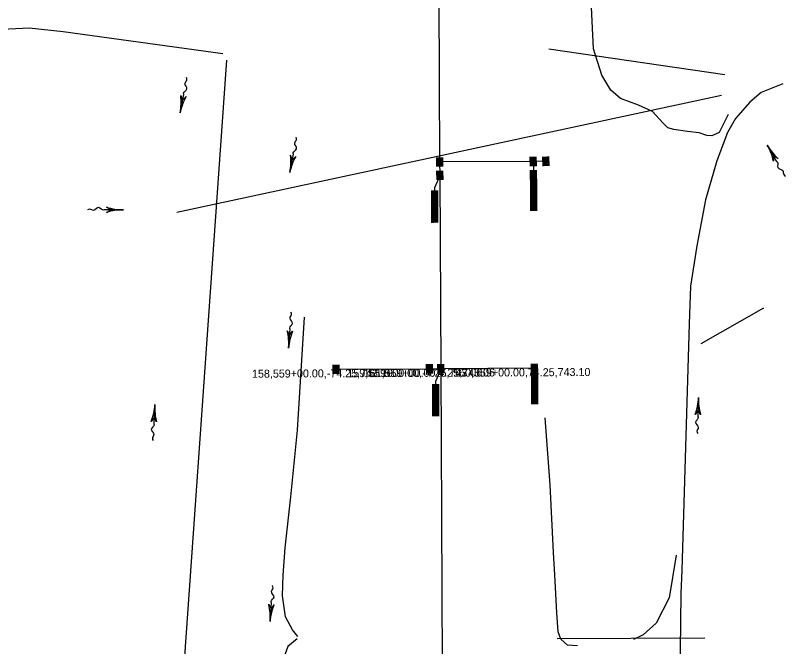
# Model space of a CAD drawing. Extents: x 593481 to 595602, y 151646 to 157396.
# Drawn here: x 594038 to 594615, y 154967 to 155440 of the extents above; entities that cross this region are included whole.
import ezdxf

# ---------------------------------------------------------------- set-up
doc = ezdxf.new("R2010")
doc.units = 0
for name, color, linetype in [('P_ALI_50_Equation', 7, 'Continuous'), ('P_DRN_Flow', 7, 'Continuous'), ('P_DRN_Inlet', 7, 'Continuous'), ('P_DRN_Pipes', 7, 'Continuous'), ('P_DRN_SS_UG', 7, 'Continuous')]:
    doc.layers.add(name, color=color, linetype=linetype)

msp = doc.modelspace()

# ---------------------------------------------------------------- linework, layer by layer
at = {"layer": 'P_DRN_Flow'}
for p, q in [((594161.19, 155367.03), (594163.89, 155380.89)), ((594601.12, 155342.88), (594608.19, 155330.65)), ((594243.38, 155322.25), (594246.08, 155336.12)), ((594118.75, 155294.28), (594104.62, 155294.42)), ((594242.48, 155190.75), (594243.54, 155204.84)), ((594142.3, 155148.35), (594141.41, 155134.25)), ((594549.65, 155153.69), (594549.17, 155139.57)), ((594228.61, 154985.82), (594229.67, 154999.91))]:
    msp.add_line(p, q, dxfattribs=at)
for points in [[(594161.67, 155379.97), (594163.02, 155376.45), (594165.59, 155379.21)], [(594243.86, 155335.19), (594245.21, 155331.67), (594247.79, 155334.43)], [(594609.26, 155332.81), (594605.93, 155334.58), (594605.8, 155330.8)], [(594105.94, 155292.41), (594109.16, 155294.38), (594105.97, 155296.41)], [(594241.45, 155203.66), (594243.2, 155200.32), (594245.44, 155203.37)], [(594551.21, 155140.83), (594549.32, 155144.1), (594547.22, 155140.96)], [(594143.49, 155135.45), (594141.7, 155138.77), (594139.5, 155135.7)], [(594227.57, 154998.73), (594229.32, 154995.39), (594231.56, 154998.44)]]:
    msp.add_lwpolyline(points, dxfattribs=at)
for centre, start, end in [((594120, 155375.03), 349.00666, 6.76898), ((594202.38, 155359.02), 151.24434, 169.00666), ((594637.44, 155363.89), 210.05001, 227.81233), ((594564.8, 155321.87), 12.2877, 30.05001), ((594202.2, 155330.25), 349.00666, 6.76898), ((594284.57, 155314.25), 151.24434, 169.00666), ((594118.34, 155252.33), 89.4352, 107.19752), ((594119.17, 155336.24), 251.67288, 269.4352), ((594200.65, 155193.9), 355.6942, 13.45652), ((594284.32, 155187.6), 157.93188, 175.6942), ((594100.43, 155151), 338.61546, 356.37778), ((594184.17, 155145.7), 176.37778, 194.1401), ((594507.72, 155155.12), 340.28381, 358.04613), ((594591.58, 155152.26), 178.04613, 195.80845), ((594186.77, 154988.97), 355.6942, 13.45652), ((594270.44, 154982.67), 157.93188, 175.6942)]:
    msp.add_arc(centre, 41.96, start, end, dxfattribs=at)
for points in [[(594163.89, 155380.9), (594163.73, 155381.73), (594166.26, 155384.91), (594164.86, 155389.18), (594166.32, 155391.78), (594166.03, 155393.59)], [(594246.08, 155336.12), (594245.92, 155336.95), (594248.46, 155340.13), (594247.05, 155344.4), (594248.51, 155347), (594248.22, 155348.81)], [(594608.19, 155330.65), (594608.86, 155330.13), (594609.04, 155326.06), (594612.9, 155323.76), (594613.5, 155320.85), (594614.91, 155319.67)], [(594104.62, 155294.42), (594103.84, 155294.12), (594100.24, 155296.03), (594096.3, 155293.88), (594093.48, 155294.85), (594091.75, 155294.24)], [(594243.54, 155204.84), (594243.29, 155205.65), (594245.44, 155209.11), (594243.54, 155213.19), (594244.69, 155215.93), (594244.2, 155217.7)], [(594549.17, 155139.57), (594549.45, 155138.77), (594547.45, 155135.23), (594549.51, 155131.23), (594548.47, 155128.44), (594549.04, 155126.69)], [(594141.41, 155134.25), (594141.67, 155133.44), (594139.56, 155129.96), (594141.51, 155125.9), (594140.39, 155123.14), (594140.91, 155121.38)], [(594229.67, 154999.91), (594229.41, 155000.72), (594231.56, 155004.18), (594229.67, 155008.26), (594230.82, 155011), (594230.32, 155012.77)]]:
    msp.add_spline(points, degree=3, dxfattribs=at)
at = {"layer": 'P_DRN_Inlet'}
for p, q in [((594353.65, 155326.8), (594353.62, 155333.67)), ((594354.55, 155326.8), (594354.52, 155333.67)), ((594355.45, 155326.8), (594355.42, 155333.68)), ((594356.35, 155326.81), (594356.32, 155333.68)), ((594357.25, 155326.81), (594357.22, 155333.69)), ((594358.15, 155326.82), (594358.12, 155333.69)), ((594423.65, 155327.15), (594423.62, 155334.03)), ((594424.55, 155327.16), (594424.52, 155334.03)), ((594425.45, 155327.16), (594425.42, 155334.04)), ((594426.35, 155327.17), (594426.32, 155334.04)), ((594427.25, 155327.17), (594427.22, 155334.05)), ((594428.15, 155327.18), (594428.12, 155334.05)), ((594433.28, 155327.15), (594432.9, 155334.01)), ((594434.18, 155327.2), (594433.8, 155334.06)), ((594435.08, 155327.24), (594434.7, 155334.11)), ((594435.98, 155327.29), (594435.6, 155334.16)), ((594436.88, 155327.34), (594436.5, 155334.21)), ((594437.78, 155327.39), (594437.4, 155334.26)), ((594353.7, 155316.81), (594353.67, 155323.68)), ((594354.6, 155316.81), (594354.57, 155323.68)), ((594355.5, 155316.81), (594355.47, 155323.69)), ((594356.4, 155316.82), (594356.37, 155323.69)), ((594357.3, 155316.82), (594357.27, 155323.7)), ((594358.2, 155316.83), (594358.17, 155323.7)), ((594423.72, 155317.19), (594423.69, 155324.07)), ((594424.62, 155317.2), (594424.59, 155324.07)), ((594425.52, 155317.2), (594425.49, 155324.08)), ((594426.42, 155317.21), (594426.39, 155324.08)), ((594427.32, 155317.21), (594427.29, 155324.09)), ((594428.22, 155317.22), (594428.19, 155324.09)), ((594423.72, 155317.63), (594423.84, 155293.63)), ((594424.62, 155317.64), (594424.74, 155293.64)), ((594425.52, 155317.64), (594425.64, 155293.64)), ((594426.42, 155317.64), (594426.54, 155293.65)), ((594427.32, 155317.65), (594427.44, 155293.65)), ((594428.22, 155317.65), (594428.34, 155293.65)), ((594349.49, 155308.73), (594349.61, 155284.73)), ((594350.39, 155308.73), (594350.51, 155284.73)), ((594351.29, 155308.73), (594351.41, 155284.74)), ((594352.19, 155308.74), (594352.31, 155284.74)), ((594353.09, 155308.74), (594353.21, 155284.74)), ((594353.99, 155308.75), (594354.11, 155284.75)), ((594275.95, 155171.39), (594275.91, 155178.27)), ((594276.85, 155171.4), (594276.81, 155178.27)), ((594277.75, 155171.4), (594277.71, 155178.28)), ((594278.65, 155171.41), (594278.61, 155178.28)), ((594279.55, 155171.41), (594279.51, 155178.29)), ((594280.45, 155171.42), (594280.41, 155178.29)), ((594345.95, 155171.75), (594345.91, 155178.63)), ((594346.85, 155171.76), (594346.81, 155178.63)), ((594347.75, 155171.76), (594347.71, 155178.64)), ((594348.65, 155171.77), (594348.61, 155178.64)), ((594349.55, 155171.77), (594349.51, 155178.65)), ((594350.45, 155171.78), (594350.41, 155178.65)), ((594354.45, 155171.8), (594354.41, 155178.67)), ((594355.35, 155171.8), (594355.31, 155178.68)), ((594356.25, 155171.81), (594356.21, 155178.68)), ((594357.15, 155171.81), (594357.11, 155178.69)), ((594358.05, 155171.82), (594358.01, 155178.69)), ((594358.95, 155171.82), (594358.91, 155178.69)), ((594424.45, 155172.16), (594424.41, 155179.03)), ((594425.35, 155172.16), (594425.31, 155179.04)), ((594426.25, 155172.17), (594426.21, 155179.04)), ((594427.15, 155172.17), (594427.11, 155179.05)), ((594428.05, 155172.17), (594428.01, 155179.05)), ((594428.95, 155172.18), (594428.91, 155179.05)), ((594424.44, 155172.59), (594424.56, 155148.6)), ((594425.34, 155172.6), (594425.46, 155148.6)), ((594426.24, 155172.6), (594426.36, 155148.6)), ((594427.14, 155172.61), (594427.26, 155148.61)), ((594428.04, 155172.61), (594428.16, 155148.61)), ((594428.94, 155172.62), (594429.06, 155148.62)), ((594350.22, 155163.67), (594350.34, 155139.67)), ((594351.12, 155163.68), (594351.24, 155139.68)), ((594352.02, 155163.68), (594352.14, 155139.68)), ((594352.92, 155163.69), (594353.04, 155139.69)), ((594353.82, 155163.69), (594353.94, 155139.69)), ((594354.72, 155163.7), (594354.84, 155139.7))]:
    msp.add_line(p, q, dxfattribs=at)
for points in [[(594356.89, 155329.25), (594356.88, 155331.25), (594354.88, 155331.24), (594354.89, 155329.24)], [(594426.89, 155329.61), (594426.88, 155331.61), (594424.88, 155331.6), (594424.89, 155329.6)], [(594436.39, 155329.76), (594436.28, 155331.75), (594434.29, 155331.65), (594434.4, 155329.65)], [(594356.94, 155319.26), (594356.93, 155321.26), (594354.93, 155321.25), (594354.94, 155319.25)], [(594426.96, 155319.65), (594426.95, 155321.65), (594424.95, 155321.64), (594424.96, 155319.64)], [(594425, 155312.91), (594425.07, 155298.37), (594427.07, 155298.38), (594427, 155312.92)], [(594350.76, 155304.01), (594350.84, 155289.46), (594352.84, 155289.47), (594352.76, 155304.02)], [(594279.19, 155173.85), (594279.18, 155175.85), (594277.18, 155175.84), (594277.19, 155173.84)], [(594349.19, 155174.21), (594349.18, 155176.21), (594347.18, 155176.2), (594347.19, 155174.2)], [(594357.69, 155174.25), (594357.68, 155176.25), (594355.68, 155176.24), (594355.69, 155174.24)], [(594427.69, 155174.61), (594427.68, 155176.61), (594425.68, 155176.6), (594425.69, 155174.6)], [(594425.71, 155167.87), (594425.79, 155153.33), (594427.79, 155153.34), (594427.71, 155167.88)], [(594351.49, 155158.95), (594351.57, 155144.41), (594353.57, 155144.42), (594353.49, 155158.96)]]:
    msp.add_lwpolyline(points, close=True, dxfattribs=at)
at = {"layer": 'P_DRN_Pipes'}
for p, q in [((594437.6, 155415.01), (594569.29, 155395.66)), ((594158.67, 155292.68), (594566.79, 155380.23)), ((594551.54, 155194.26), (594598.53, 155220.88)), ((594443.69, 154973.11), (594554.46, 154973.67))]:
    msp.add_line(p, q, dxfattribs=at)
at = {"layer": 'P_DRN_SS_UG'}
for p, q in [((594355.89, 155330.24), (594355.09, 155485.25)), ((594425.88, 155330.6), (594355.89, 155330.24)), ((594355.94, 155320.25), (594355.89, 155330.24)), ((594435.34, 155330.7), (594425.88, 155330.6)), ((594425.88, 155330.6), (594425.94, 155320.6)), ((594356.68, 155175.25), (594355.94, 155320.25)), ((594425.96, 155319.64), (594425.97, 155317.64)), ((594278.18, 155174.84), (594348.18, 155175.2)), ((594348.18, 155175.2), (594356.68, 155175.25)), ((594426.68, 155175.61), (594356.68, 155175.25)), ((594358.22, 154875.25), (594356.68, 155175.25)), ((594426.68, 155175.61), (594426.7, 155172.61))]:
    msp.add_line(p, q, dxfattribs=at)
for points in [[(594571.92, 155365.74), (594565.14, 155352.43), (594559.64, 155349.73), (594555.87, 155350.12), (594550.25, 155352.04), (594541.37, 155353.15), (594531.15, 155354.6), (594526.59, 155355.9), (594522.9, 155359.56), (594515.29, 155368.06), (594504.61, 155372.79), (594491.24, 155377.87), (594483.84, 155384), (594477.1, 155395.15), (594470.86, 155414.95), (594468.94, 155456.73), (594466.21, 155498.03)], [(594193.09, 155411.34), (594073.54, 155427.86), (594048.1, 155430.58), (594022.56, 155429.15), (594004.52, 155425.45), (593990.2, 155419.58), (593976.72, 155409.53), (593963.18, 155397.41), (593953.35, 155382.07), (593943.75, 155338.68), (593941.24, 155313.82), (593931.56, 155304.71), (593921.12, 155302.9), (593896.63, 155305.59), (593891.96, 155307.79), (593879.74, 155310.17), (593860.02, 155314.83), (593844.02, 155317.31), (593827.14, 155321.89), (593814.99, 155327.39)], [(594195.87, 155406.63), (594155.86, 154839.17), (594136.12, 154647.32), (594125.75, 154586.3), (594119.28, 154562.31), (594104.8, 154521.76), (594093.35, 154507.25), (594075.71, 154498.55), (594048.65, 154492.71), (593981.57, 154485.26), (593546.85, 154493.19), (593538.17, 154494.28), (593526.38, 154497.62), (593514.24, 154502.72), (593501.23, 154504.79), (593491.32, 154504.17), (593484.5, 154500.86), (593481.17, 154494.41)], [(594612.95, 155388.89), (594596.71, 155382.2), (594588.1, 155375.16), (594577.39, 155362.81), (594571.35, 155352.38), (594563.26, 155330.97), (594554.94, 155301.9), (594548.34, 155267.44), (594543.77, 155237.13), (594542.73, 155208.88), (594537.26, 155024.38), (594536.51, 155006.73), (594535.72, 154943.23), (594533.09, 154881.6), (594531.45, 154816.64), (594529.67, 154746.17)], [(594355.94, 155320.25), (594351.74, 155310.74), (594351.75, 155308.74)], [(594249.5, 154974.47), (594245.36, 154979.68), (594240.25, 154989.23), (594237.97, 155005.19), (594238.36, 155020.5), (594239.95, 155041.07), (594244.13, 155079.25), (594249.14, 155129.18), (594254.49, 155213.86)], [(594356.68, 155175.25), (594352.48, 155165.69), (594352.49, 155163.69)], [(594459.03, 154967.51), (594451.56, 154968.01), (594446.5, 154972.57), (594444.41, 154978.14), (594443.43, 154992.33), (594442.07, 155020.78), (594440.92, 155037.43), (594438.56, 155088.15), (594434.63, 155138.37)], [(594532.95, 155035.61), (594527.56, 155003.52), (594517.93, 154984.63), (594508.17, 154975.76), (594500.89, 154972.46)], [(594248.94, 154972.9), (594241.91, 154967.19), (594238.79, 154958.94), (594235.75, 154930.84), (594230.88, 154901.44), (594227.52, 154859.43), (594221.1, 154817.5), (594214.83, 154781.45), (594209.84, 154735.27), (594200.1, 154653.01), (594191.65, 154590.92), (594189.63, 154541.3), (594190.82, 154497.49), (594193.99, 154473.57)]]:
    msp.add_lwpolyline(points, dxfattribs=at)

# ---------------------------------------------------------------- texts
at = {"layer": 'P_ALI_50_Equation'}
for s, p in [('158,559+00.00,-74.25,743.10', (594215.08, 155168.52)), ('159,559+00.00,-4.25,743.06', (594286.52, 155168.89)), ('161,559+00.00,4.25,743.06', (594298.75, 155168.95)), ('160,559+00.00,74.25,743.10', (594365.79, 155169.29))]:
    msp.add_text(s, height=6, rotation=0.29409, dxfattribs=at).set_placement(p)

doc.saveas('drawing.dxf')
